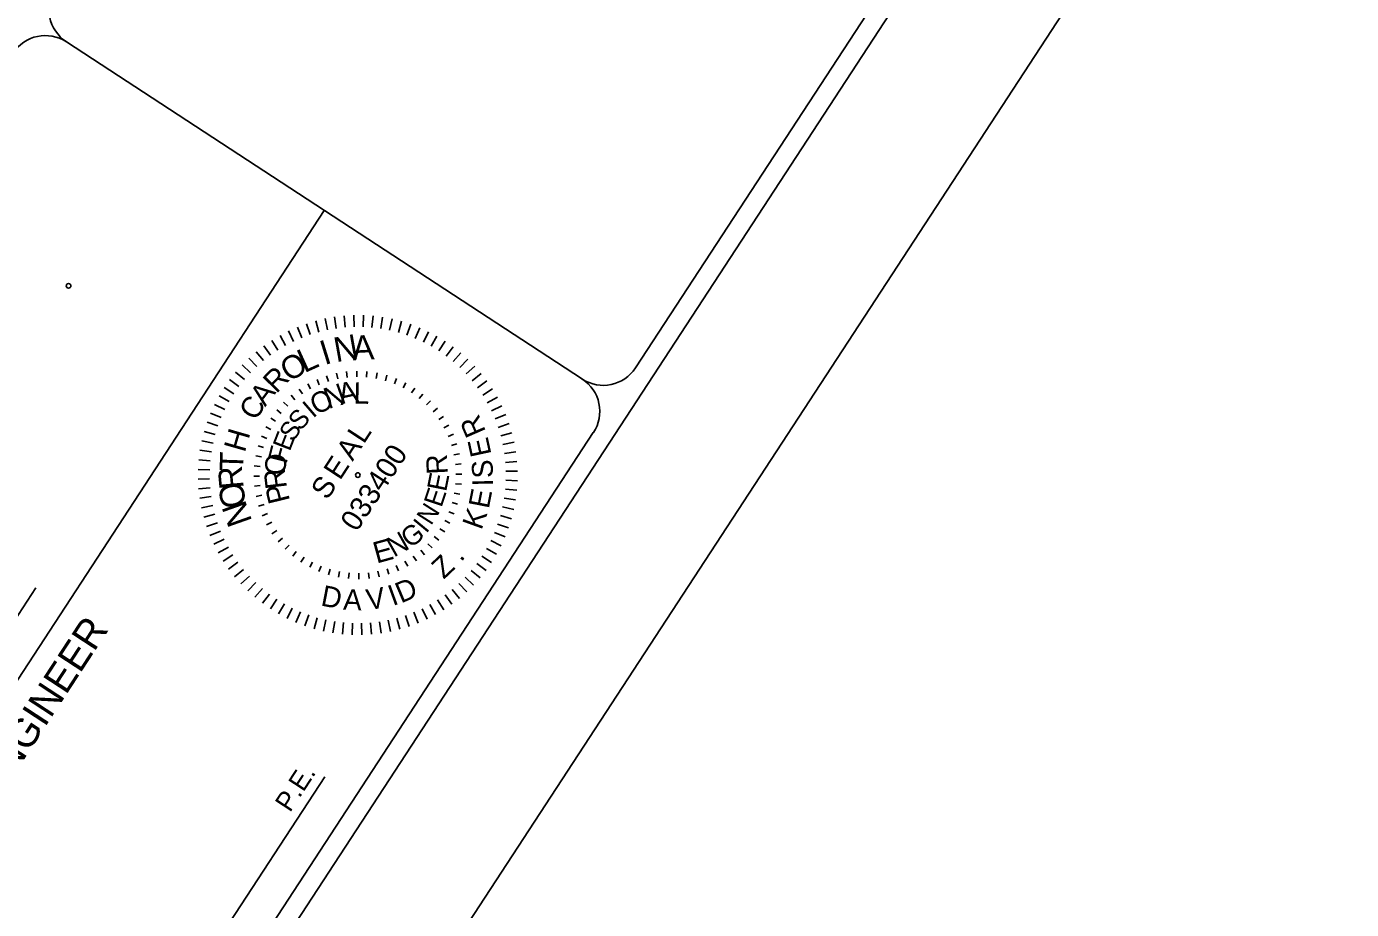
# Model space of a CAD drawing. Extents: x 1190029 to 2382315, y 163128 to 334830.
# Drawn here: x 2381627 to 2382315, y 332651 to 333109 of the extents above; entities that cross this region are included whole.
import ezdxf

# ---------------------------------------------------------------- set-up
doc = ezdxf.new("R2010")
doc.units = 0
for name, color, linetype in [('Exist Right of Way Width CELL', 7, 'Continuous'), ('Exist Utilities Telephone UG Cable SUE LOS B', 7, 'Continuous'), ('Exist Utilities Telephone UG FO SUE LOS B Text', 7, 'Continuous'), ('z - Construction', 7, 'Continuous')]:
    doc.layers.add(name, color=color, linetype=linetype)

msp = doc.modelspace()

# ---------------------------------------------------------------- linework, layer by layer
at = {"layer": 'Exist Right of Way Width CELL'}
for p, q in [((2381782.77, 332951.57), (2381781.54, 332957.43)), ((2381787.35, 332952.38), (2381786.48, 332958.31)), ((2381791.97, 332952.92), (2381791.46, 332958.9)), ((2381796.61, 332953.17), (2381796.46, 332959.17)), ((2381801.26, 332953.15), (2381801.47, 332959.14)), ((2381805.9, 332952.85), (2381806.47, 332958.82)), ((2381810.51, 332952.26), (2381811.44, 332958.18)), ((2381815.08, 332951.4), (2381816.36, 332957.26)), ((2381765.2, 332945.6), (2381762.61, 332951.01)), ((2381769.45, 332947.49), (2381767.19, 332953.04)), ((2381773.81, 332949.12), (2381771.88, 332954.79)), ((2381778.25, 332950.48), (2381776.67, 332956.26)), ((2381819.59, 332950.27), (2381821.22, 332956.03)), ((2381824.01, 332948.86), (2381826, 332954.52)), ((2381828.35, 332947.19), (2381830.68, 332952.72)), ((2381832.58, 332945.26), (2381835.23, 332950.64)), ((2381753.25, 332938.45), (2381749.72, 332943.31)), ((2381757.09, 332941.08), (2381753.86, 332946.13)), ((2381761.08, 332943.46), (2381758.16, 332948.7)), ((2381836.69, 332943.08), (2381839.66, 332948.29)), ((2381840.65, 332940.65), (2381843.93, 332945.67)), ((2381844.47, 332937.99), (2381848.04, 332942.81)), ((2381746.08, 332932.54), (2381741.99, 332936.93)), ((2381749.58, 332935.61), (2381745.76, 332940.24)), ((2381848.11, 332935.11), (2381851.97, 332939.7)), ((2381851.57, 332932.01), (2381855.71, 332936.36)), ((2381739.68, 332925.81), (2381735.09, 332929.68)), ((2381742.78, 332929.28), (2381738.43, 332933.41)), ((2381788.1, 332926.13), (2381787.48, 332929.07)), ((2381793.04, 332926.92), (2381792.72, 332929.9)), ((2381798.03, 332927.21), (2381798, 332930.21)), ((2381803.03, 332927.02), (2381803.3, 332930)), ((2381807.99, 332926.33), (2381808.54, 332929.28)), ((2381854.84, 332928.7), (2381859.23, 332932.8)), ((2381857.91, 332925.21), (2381862.53, 332929.02)), ((2381736.79, 332922.17), (2381731.98, 332925.75)), ((2381774.06, 332920.95), (2381772.62, 332923.58)), ((2381778.56, 332923.14), (2381777.39, 332925.89)), ((2381783.26, 332924.87), (2381782.36, 332927.73)), ((2381812.85, 332925.16), (2381813.7, 332928.04)), ((2381817.57, 332923.53), (2381818.7, 332926.31)), ((2381822.12, 332921.44), (2381823.5, 332924.09)), ((2381860.76, 332921.54), (2381865.61, 332925.07)), ((2381731.71, 332914.39), (2381726.5, 332917.36)), ((2381734.13, 332918.35), (2381729.11, 332921.63)), ((2381765.81, 332915.31), (2381763.89, 332917.62)), ((2381769.8, 332918.34), (2381768.11, 332920.82)), ((2381826.43, 332918.9), (2381828.07, 332921.41)), ((2381830.48, 332915.97), (2381832.36, 332918.3)), ((2381863.38, 332917.7), (2381868.43, 332920.93)), ((2381865.77, 332913.71), (2381871, 332916.63)), ((2381727.6, 332906.05), (2381722.07, 332908.38)), ((2381729.52, 332910.28), (2381724.15, 332912.93)), ((2381758.82, 332908.18), (2381756.48, 332910.06)), ((2381762.14, 332911.92), (2381760, 332914.02)), ((2381834.22, 332912.64), (2381836.32, 332914.79)), ((2381837.62, 332908.97), (2381839.92, 332910.9)), ((2381867.91, 332909.58), (2381873.31, 332912.18)), ((2381725.93, 332901.71), (2381720.27, 332903.7)), ((2381755.88, 332904.13), (2381753.37, 332905.77)), ((2381840.64, 332904.99), (2381843.11, 332906.68)), ((2381843.25, 332900.72), (2381845.88, 332902.16)), ((2381869.79, 332905.34), (2381875.34, 332907.6)), ((2381871.41, 332900.98), (2381877.09, 332902.91)), ((2381724.52, 332897.29), (2381718.75, 332898.92)), ((2381751.26, 332895.28), (2381748.48, 332896.4)), ((2381753.35, 332899.82), (2381750.7, 332901.21)), ((2381845.43, 332896.22), (2381848.19, 332897.4)), ((2381872.77, 332896.53), (2381878.56, 332898.11)), ((2381722.52, 332888.21), (2381716.6, 332889.14)), ((2381723.39, 332892.78), (2381717.53, 332894.06)), ((2381749.63, 332890.55), (2381746.75, 332891.39)), ((2381847.17, 332891.53), (2381850.03, 332892.43)), ((2381873.87, 332892.01), (2381879.73, 332893.24)), ((2381874.68, 332887.44), (2381880.61, 332888.31)), ((2381721.94, 332883.6), (2381715.97, 332884.17)), ((2381747.77, 332880.73), (2381744.78, 332881)), ((2381748.46, 332885.69), (2381745.51, 332886.24)), ((2381848.43, 332886.69), (2381851.37, 332887.3)), ((2381849.22, 332881.75), (2381852.2, 332882.07)), ((2381875.22, 332882.82), (2381881.19, 332883.33)), ((2381721.61, 332874.31), (2381715.62, 332874.16)), ((2381721.64, 332878.96), (2381715.64, 332879.17)), ((2381747.57, 332875.73), (2381744.58, 332875.7)), ((2381849.51, 332876.75), (2381852.51, 332876.78)), ((2381875.47, 332878.18), (2381881.47, 332878.33)), ((2381721.87, 332869.67), (2381715.9, 332869.15)), ((2381747.87, 332870.74), (2381744.9, 332870.42)), ((2381849.32, 332871.76), (2381852.3, 332871.49)), ((2381875.15, 332868.89), (2381881.12, 332868.32)), ((2381875.45, 332873.53), (2381881.44, 332873.32)), ((2381722.4, 332865.05), (2381716.47, 332864.18)), ((2381723.22, 332860.47), (2381717.35, 332859.25)), ((2381748.66, 332865.8), (2381745.72, 332865.19)), ((2381749.92, 332860.96), (2381747.06, 332860.06)), ((2381847.47, 332861.93), (2381850.34, 332861.1)), ((2381848.63, 332866.8), (2381851.58, 332866.25)), ((2381874.56, 332864.28), (2381880.48, 332863.34)), ((2381724.31, 332855.95), (2381718.53, 332854.38)), ((2381751.65, 332856.27), (2381748.89, 332855.09)), ((2381845.83, 332857.21), (2381848.61, 332856.09)), ((2381872.57, 332855.2), (2381878.34, 332853.56)), ((2381873.7, 332859.71), (2381879.56, 332858.42)), ((2381725.67, 332851.51), (2381719.99, 332849.58)), ((2381727.3, 332847.15), (2381721.75, 332844.89)), ((2381753.83, 332851.77), (2381751.21, 332850.32)), ((2381756.45, 332847.5), (2381753.98, 332845.81)), ((2381841.2, 332848.35), (2381843.71, 332846.71)), ((2381843.74, 332852.67), (2381846.39, 332851.28)), ((2381869.49, 332846.44), (2381875.02, 332844.11)), ((2381871.16, 332850.77), (2381876.82, 332848.79)), ((2381729.18, 332842.91), (2381723.78, 332840.31)), ((2381759.47, 332843.52), (2381757.17, 332841.58)), ((2381762.86, 332839.84), (2381760.77, 332837.7)), ((2381834.94, 332840.57), (2381837.09, 332838.47)), ((2381838.27, 332844.3), (2381840.6, 332842.43)), ((2381867.56, 332842.21), (2381872.94, 332839.56)), ((2381731.32, 332838.78), (2381726.08, 332835.86)), ((2381733.71, 332834.79), (2381728.66, 332831.56)), ((2381766.6, 332836.52), (2381764.73, 332834.19)), ((2381770.65, 332833.58), (2381769.01, 332831.07)), ((2381827.29, 332834.15), (2381828.97, 332831.67)), ((2381831.28, 332837.17), (2381833.2, 332834.87)), ((2381862.95, 332834.13), (2381867.97, 332830.85)), ((2381865.38, 332838.1), (2381870.59, 332835.13)), ((2381736.33, 332830.95), (2381731.48, 332827.42)), ((2381739.18, 332827.27), (2381734.55, 332823.46)), ((2381774.97, 332831.05), (2381773.58, 332828.4)), ((2381779.51, 332828.96), (2381778.39, 332826.18)), ((2381784.24, 332827.32), (2381783.4, 332824.44)), ((2381789.1, 332826.16), (2381788.55, 332823.21)), ((2381808.99, 332826.36), (2381809.6, 332823.42)), ((2381813.83, 332827.62), (2381814.73, 332824.76)), ((2381818.52, 332829.35), (2381819.69, 332826.59)), ((2381823.02, 332831.54), (2381824.46, 332828.91)), ((2381857.41, 332826.68), (2381862, 332822.81)), ((2381860.29, 332830.32), (2381865.11, 332826.74)), ((2381742.24, 332823.78), (2381737.85, 332819.7)), ((2381745.51, 332820.48), (2381741.38, 332816.13)), ((2381794.06, 332825.47), (2381793.79, 332822.48)), ((2381799.05, 332825.28), (2381799.08, 332822.28)), ((2381804.05, 332825.57), (2381804.37, 332822.59)), ((2381851.01, 332819.94), (2381855.09, 332815.55)), ((2381854.31, 332823.22), (2381858.65, 332819.08)), ((2381748.98, 332817.38), (2381745.11, 332812.79)), ((2381752.63, 332814.49), (2381749.04, 332809.68)), ((2381843.84, 332814.03), (2381847.37, 332809.18)), ((2381847.51, 332816.88), (2381851.33, 332812.25)), ((2381756.43, 332811.83), (2381753.15, 332806.81)), ((2381760.4, 332809.41), (2381757.43, 332804.2)), ((2381764.51, 332807.23), (2381761.85, 332801.85)), ((2381768.73, 332805.3), (2381766.41, 332799.77)), ((2381831.88, 332806.89), (2381834.48, 332801.48)), ((2381836.01, 332809.02), (2381838.93, 332803.78)), ((2381840, 332811.41), (2381843.23, 332806.36)), ((2381773.07, 332803.63), (2381771.09, 332797.97)), ((2381777.5, 332802.22), (2381775.86, 332796.46)), ((2381782.01, 332801.09), (2381780.72, 332795.23)), ((2381786.58, 332800.22), (2381785.65, 332794.3)), ((2381791.19, 332799.64), (2381790.62, 332793.67)), ((2381795.83, 332799.33), (2381795.62, 332793.34)), ((2381800.47, 332799.32), (2381800.63, 332793.32)), ((2381805.12, 332799.57), (2381805.63, 332793.59)), ((2381809.74, 332800.11), (2381810.61, 332794.18)), ((2381814.31, 332800.92), (2381815.55, 332795.05)), ((2381818.83, 332802.01), (2381820.41, 332796.23)), ((2381823.28, 332803.37), (2381825.2, 332797.69)), ((2381827.63, 332805), (2381829.9, 332799.45))]:
    msp.add_line(p, q, dxfattribs=at)
at = {"layer": 'Exist Utilities Telephone UG Cable SUE LOS B'}
for centre in [(2381648.34, 332974.44), (2381798.54, 332876.24)]:
    msp.add_circle(centre, 1.2, dxfattribs=at)
at = {"layer": 'Exist Utilities Telephone UG FO SUE LOS B Text'}
for p, q in [((2380443.25, 330620.18), (2382199.76, 333306.95)), ((2381942.73, 332931.86), (2382186.02, 333303.99)), ((2381915.14, 332925.99), (2381647.3, 333101.09)), ((2381477.22, 332548.75), (2381781.12, 333013.61)), ((2381638.82, 332466.99), (2381920.84, 332898.37)), ((2381476.53, 332580.86), (2381631.41, 332817.72)), ((2381626.56, 332482.78), (2381781.44, 332719.63))]:
    msp.add_line(p, q, dxfattribs=at)
for centre, start, end in [((2381658.15, 333117.9), 146.82484, 236.82484), ((2381636.35, 333084.35), 56.82484, 146.82484), ((2381925.99, 332942.8), 236.82484, 326.82484), ((2381904.19, 332909.25), 326.82484, 56.82484)]:
    msp.add_arc(centre, 20, start, end, dxfattribs=at)
at = {"layer": 'z - Construction'}
msp.add_line((2380454.04, 330499.63), (2382314.52, 333345.43), dxfattribs=at)

# ---------------------------------------------------------------- texts
at = {"layer": 'Exist Right of Way Width CELL'}
for s, height, rotation, p in [('I', 12.65, 17.25342, (2381781.26, 332933.25)), ('N', 12.82, 10.16419, (2381787.29, 332934.74)), ('A', 12.78, 3.07496, (2381795.95, 332935.75)), ('O', 11.92, 31.43188, (2381762.91, 332924.28)), ('L', 12.32, 24.34265, (2381770.78, 332929.06)), ('R', 11.2, 45.61034, (2381756.26, 332918.2)), ('A', 11.02, 52.69957, (2381750.42, 332911.37)), ('N', 10.96, 19.56574, (2381783.25, 332910.37)), ('A', 11.16, 12.53362, (2381789.6, 332912.45)), ('L', 11.03, 358.46938, (2381796.2, 332913.39)), ('C', 11.01, 59.7888, (2381745.77, 332903.99)), ('O', 10.64, 26.59786, (2381777.06, 332907.18)), ('S', 9.72, 47.69422, (2381768.64, 332898.78)), ('I', 9.96, 40.6621, (2381775.3, 332905.43)), ('S', 9.6, 54.72634, (2381764.81, 332893.11)), ('R', 10.8, 113.48696, (2381865.2, 332898.86)), ('H', 11.46, 73.96726, (2381739.82, 332887.55)), ('E', 9.8, 68.79058, (2381763.19, 332888.18)), ('L', 10.99, 56.82484, (2381801.64, 332891.98)), ('E', 10.8, 102.20208, (2381867.99, 332887.01)), ('T', 12.26, 88.14572, (2381739.01, 332878.1)), ('F', 10.08, 75.8227, (2381761.48, 332881.75)), ('A', 10.99, 56.82484, (2381795.85, 332883.05)), ('033400', 10.993, 56.82484, (2381798, 332846.32)), ('O', 10.78, 89.88694, (2381761.26, 332876.25)), ('E', 10.99, 56.82484, (2381789.29, 332873.09)), ('R', 10.9, 92.72208, (2381845.29, 332876.79)), ('S', 10.8, 93.58652, (2381868.92, 332874.89)), ('R', 12.6, 95.23495, (2381739.36, 332869.39)), ('R', 11.06, 96.91906, (2381761.79, 332869.6)), ('S', 10.99, 56.82484, (2381782.71, 332862.83)), ('E', 10.22, 78.65784, (2381844.4, 332867.27)), ('O', 12.81, 102.32418, (2381741, 332860.55)), ('P', 11.19, 103.95119, (2381763.43, 332862.97)), ('E', 9.9, 71.62572, (2381841.98, 332859.05)), ('E', 10.8, 79.00326, (2381866.53, 332858.38)), ('I', 10.8, 90.68997, (2381868.77, 332870.44)), ('N', 12.81, 109.41341, (2381743.83, 332852.29)), ('N', 9.6, 57.56147, (2381836.58, 332849.7)), ('I', 9.65, 50.52935, (2381834.03, 332845.6)), ('K', 10.8, 70.1583, (2381862.69, 332847.34)), ('N', 10.5, 29.43299, (2381817.28, 332833.36)), ('G', 10.15, 36.46511, (2381825.59, 332837.94)), ('E', 11.1, 15.36875, (2381808.28, 332830.25)), ('Z', 10.8, 43.49027, (2381843.17, 332821.89)), ('.', 10.8, 55.34107, (2381852.39, 332830.77)), ('D', 10.8, 349.15019, (2381778.9, 332808.58)), ('I', 10.8, 20.06205, (2381816.68, 332808.19)), ('D', 10.8, 22.9586, (2381820.92, 332809.54)), ('A', 10.8, 357.38146, (2381790.79, 332806.37)), ('V', 10.8, 8.60204, (2381803.79, 332806.09))]:
    msp.add_text(s, height=height, rotation=rotation, dxfattribs=at).set_placement(p)
at = {"layer": 'Exist Utilities Telephone UG FO SUE LOS B Text'}
for s, height, p in [('ROADWAY DESIGN ENGINEER', 14.9988, (2381507.32, 332548.13)), ('P.E.', 9.999, (2381763.33, 332700.76))]:
    msp.add_text(s, height=height, rotation=56.82484, dxfattribs=at).set_placement(p)

doc.saveas('drawing.dxf')
